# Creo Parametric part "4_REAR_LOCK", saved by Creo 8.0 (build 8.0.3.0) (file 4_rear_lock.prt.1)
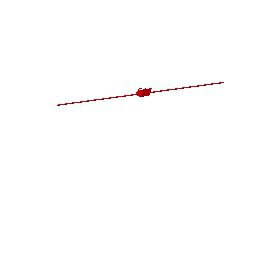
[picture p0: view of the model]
Units: millimeter Newton Second (mmNs); MM, TONNE, SECS

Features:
  1. datum plane "DTM1"
  2. datum plane "DTM2"
  3. datum plane "DTM3"
  4. coordinate system
  5. datum plane "DTM4"
  6. protrusion
  7. protrusion
  8. cut
  9. protrusion
  10. round
  11. protrusion
  12. round
  13. protrusion
  14. protrusion
  15. round
  16. round
  17. protrusion
  18. protrusion
  19. round
  20. round
  21. round

Other named items: CS0

Layers: 0_ALL_AXIS, 0_ALL_CSYS, 0_ALL_CURVES, 0_ALL_PLANES, 0_ALL_POINTS, 0_ALL_SURFS, REAR_LOCK

Surfaces: 24 plane, 21 cylinder, 7 torus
